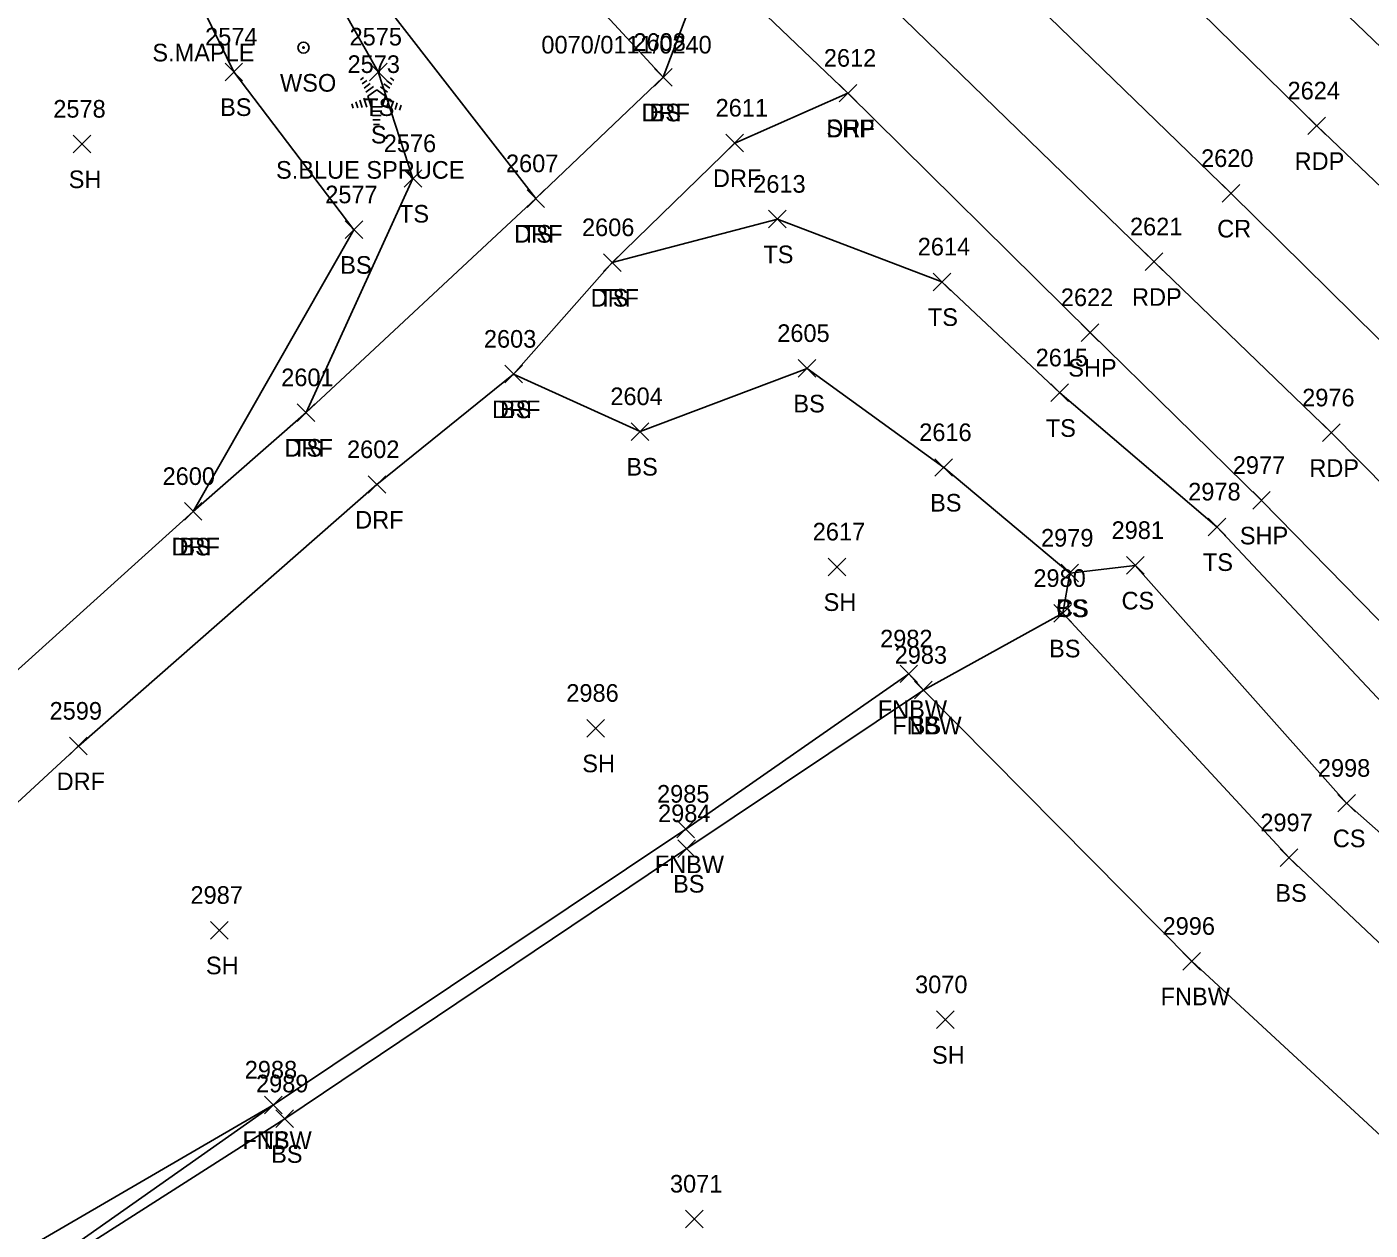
# Model space of a CAD drawing. Extents: x 1472233 to 1475777, y 540726 to 543442.
# Drawn here: x 1473688.8 to 1473841.3, y 542326.8 to 542463.4 of the extents above; entities that cross this region are included whole.
import ezdxf

# ---------------------------------------------------------------- set-up
doc = ezdxf.new("R2010")
doc.units = 0
for name, color, linetype in [('L_A', 7, 'Continuous'), ('L_C', 7, 'Continuous'), ('L_I', 7, 'Continuous'), ('L_TIC', 7, 'Continuous'), ('LELB', 7, 'Continuous'), ('LFNC', 7, 'Continuous'), ('LTC', 7, 'Continuous'), ('P_A', 7, 'Continuous'), ('P_I', 7, 'Continuous'), ('P_TIC', 7, 'Continuous'), ('PET', 7, 'Continuous'), ('PRC', 7, 'Continuous'), ('PSP', 7, 'Continuous'), ('R_A', 7, 'Continuous'), ('R_I', 7, 'Continuous'), ('R_TIC', 7, 'Continuous'), ('RDF', 7, 'Continuous'), ('S_C', 7, 'Continuous'), ('U_A', 7, 'Continuous'), ('UWV', 7, 'Continuous')]:
    doc.layers.add(name, color=color, linetype=linetype)

msp = doc.modelspace()

# ---------------------------------------------------------------- linework, layer by layer
at = {"layer": 'L_TIC'}
for points in [[(1473711.29, 542457.24), (1473713.29, 542459.24)], [(1473713.29, 542457.24), (1473711.29, 542459.24)], [(1473727.69, 542457.24), (1473729.69, 542459.24)], [(1473729.69, 542457.24), (1473727.69, 542459.24)], [(1473760.05, 542456.63), (1473762.05, 542458.63)], [(1473762.05, 542456.63), (1473760.05, 542458.63)], [(1473694.05, 542449.05), (1473696.05, 542451.05)], [(1473696.05, 542449.05), (1473694.05, 542451.05)], [(1473731.63, 542445.14), (1473733.63, 542447.14)], [(1473733.63, 542445.14), (1473731.63, 542447.14)], [(1473745.58, 542442.86), (1473747.58, 542444.86)], [(1473747.58, 542442.86), (1473745.58, 542444.86)], [(1473773, 542440.53), (1473775, 542442.53)], [(1473775, 542440.53), (1473773, 542442.53)], [(1473724.93, 542439.33), (1473726.93, 542441.33)], [(1473726.93, 542439.33), (1473724.93, 542441.33)], [(1473754.26, 542435.6), (1473756.26, 542437.6)], [(1473756.26, 542435.6), (1473754.26, 542437.6)], [(1473791.68, 542433.41), (1473793.68, 542435.41)], [(1473793.68, 542433.41), (1473791.68, 542435.41)], [(1473791.68, 542433.41), (1473793.68, 542435.41)], [(1473793.68, 542433.41), (1473791.68, 542435.41)], [(1473743.06, 542422.94), (1473745.06, 542424.94)], [(1473745.06, 542422.94), (1473743.06, 542424.94)], [(1473776.37, 542423.59), (1473778.37, 542425.59)], [(1473778.37, 542423.59), (1473776.37, 542425.59)], [(1473805.07, 542420.82), (1473807.07, 542422.82)], [(1473807.07, 542420.82), (1473805.07, 542422.82)], [(1473719.49, 542418.57), (1473721.49, 542420.57)], [(1473721.49, 542418.57), (1473719.49, 542420.57)], [(1473757.42, 542416.42), (1473759.42, 542418.42)], [(1473759.42, 542416.42), (1473757.42, 542418.42)], [(1473791.9, 542412.34), (1473793.9, 542414.34)], [(1473793.9, 542412.34), (1473791.9, 542414.34)], [(1473791.9, 542412.34), (1473793.9, 542414.34)], [(1473793.9, 542412.34), (1473791.9, 542414.34)], [(1473706.67, 542407.36), (1473708.67, 542409.36)], [(1473708.67, 542407.36), (1473706.67, 542409.36)], [(1473822.91, 542405.6), (1473824.91, 542407.6)], [(1473824.91, 542405.6), (1473822.91, 542407.6)], [(1473779.76, 542401.06), (1473781.76, 542403.06)], [(1473781.76, 542401.06), (1473779.76, 542403.06)], [(1473813.64, 542401.23), (1473815.64, 542403.23)], [(1473815.64, 542401.23), (1473813.64, 542403.23)], [(1473806.21, 542400.36), (1473808.21, 542402.36)], [(1473808.21, 542400.36), (1473806.21, 542402.36)], [(1473806.21, 542400.36), (1473808.21, 542402.36)], [(1473808.21, 542400.36), (1473806.21, 542402.36)], [(1473805.41, 542395.79), (1473807.41, 542397.79)], [(1473807.41, 542395.79), (1473805.41, 542397.79)], [(1473805.41, 542395.79), (1473807.41, 542397.79)], [(1473807.41, 542395.79), (1473805.41, 542397.79)], [(1473787.93, 542388.92), (1473789.93, 542390.92)], [(1473789.93, 542388.92), (1473787.93, 542390.92)], [(1473787.93, 542388.92), (1473789.93, 542390.92)], [(1473789.93, 542388.92), (1473787.93, 542390.92)], [(1473789.58, 542387.07), (1473791.58, 542389.07)], [(1473791.58, 542387.07), (1473789.58, 542389.07)], [(1473789.58, 542387.07), (1473791.58, 542389.07)], [(1473791.58, 542387.07), (1473789.58, 542389.07)], [(1473752.36, 542382.75), (1473754.36, 542384.75)], [(1473754.36, 542382.75), (1473752.36, 542384.75)], [(1473837.63, 542374.24), (1473839.63, 542376.24)], [(1473839.63, 542374.24), (1473837.63, 542376.24)], [(1473762.6, 542371.3), (1473764.6, 542373.3)], [(1473764.6, 542371.3), (1473762.6, 542373.3)], [(1473762.72, 542369.09), (1473764.72, 542371.09)], [(1473764.72, 542369.09), (1473762.72, 542371.09)], [(1473831.1, 542368.05), (1473833.1, 542370.05)], [(1473833.1, 542368.05), (1473831.1, 542370.05)], [(1473709.63, 542359.82), (1473711.63, 542361.82)], [(1473711.63, 542359.82), (1473709.63, 542361.82)], [(1473820.05, 542356.3), (1473822.05, 542358.3)], [(1473822.05, 542356.3), (1473820.05, 542358.3)], [(1473792.07, 542349.67), (1473794.07, 542351.67)], [(1473794.07, 542349.67), (1473792.07, 542351.67)], [(1473715.79, 542339.99), (1473717.79, 542341.99)], [(1473717.79, 542339.99), (1473715.79, 542341.99)], [(1473715.79, 542339.99), (1473717.79, 542341.99)], [(1473717.79, 542339.99), (1473715.79, 542341.99)], [(1473717.07, 542338.42), (1473719.07, 542340.42)], [(1473719.07, 542338.42), (1473717.07, 542340.42)], [(1473763.58, 542327.05), (1473765.58, 542329.05)], [(1473765.58, 542327.05), (1473763.58, 542329.05)]]:
    msp.add_lwpolyline(points, dxfattribs=at)
at = {"layer": 'LELB'}
for points in [[(1473694.52, 542523.59), (1473709.48, 542491.61), (1473746.58, 542443.86)], [(1473694.52, 542523.59), (1473734.71, 542486.17), (1473761.05, 542457.63)], [(1473673.23, 542513.08), (1473689.8, 542504.27), (1473712.29, 542458.24), (1473725.93, 542440.33), (1473707.67, 542408.36)], [(1473709.48, 542491.61), (1473720.94, 542471.94), (1473728.69, 542458.24), (1473732.63, 542446.14), (1473720.49, 542419.57)], [(1473755.26, 542436.6), (1473774, 542441.53), (1473792.68, 542434.41)], [(1473792.68, 542434.41), (1473806.07, 542421.82), (1473823.91, 542406.6), (1473846.8, 542382.23), (1473883.89, 542347.59), (1473923.06, 542310.01), (1473939.92, 542294.2), (1473980.53, 542254.94), (1474015.06, 542222.57), (1474049.98, 542187.95), (1474097.37, 542139.4), (1474126.3, 542113.18), (1474158.64, 542082.55), (1474192.68, 542050.26)], [(1473744.06, 542423.94), (1473758.42, 542417.42), (1473777.37, 542424.59), (1473792.9, 542413.34)], [(1473792.9, 542413.34), (1473807.21, 542401.36), (1473806.41, 542396.79), (1473832.1, 542369.05), (1473869.82, 542333.48), (1473905.79, 542295.44), (1473926.1, 542278.34), (1473963.69, 542239.58), (1474000.68, 542206.05), (1474031.52, 542172.06), (1474077.5, 542132.04), (1474083.86, 542123.86), (1474077.32, 542112.31)], [(1473807.21, 542401.36), (1473814.64, 542402.23), (1473838.63, 542375.24), (1473877.39, 542340.99), (1473914.07, 542301.43), (1473934.96, 542288.13), (1473972.64, 542247.92), (1474010.39, 542216.95), (1474043.01, 542181.58), (1474086.64, 542136.88), (1474094.57, 542127.48), (1474117.17, 542110.79), (1474125.34, 542095.52), (1474154.93, 542062.15)], [(1473806.41, 542396.79), (1473790.58, 542388.07), (1473763.72, 542370.09), (1473718.07, 542339.42), (1473679.7, 542314.95)], [(1473716.79, 542340.99), (1473677.93, 542318.4), (1473636, 542289.03), (1473572.72, 542255.02), (1473538.31, 542235.47), (1473487.79, 542200.93), (1473468.56, 542187.86), (1473453.73, 542179.12), (1473444.66, 542179)]]:
    msp.add_lwpolyline(points, dxfattribs=at)
at = {"layer": 'LFNC'}
for points in [[(1473788.93, 542389.92), (1473763.6, 542372.3), (1473716.79, 542340.99), (1473679.7, 542314.95), (1473636.91, 542286.2), (1473580.88, 542249.71), (1473545.42, 542224.8), (1473490.4, 542188.54), (1473453.7, 542165.81)], [(1473788.93, 542389.92), (1473790.58, 542388.07), (1473821.05, 542357.3), (1473858.54, 542322.69), (1473895.28, 542286.17), (1473916.03, 542266.76), (1473948.88, 542234.28), (1473995.44, 542188.5), (1474018.95, 542165.4), (1474046.18, 542138.58), (1474056.8, 542130.76), (1474077.32, 542112.31), (1474080.42, 542109.11)]]:
    msp.add_lwpolyline(points, dxfattribs=at)
at = {"layer": 'LTC'}
for p, q in [((1473726.66, 542457.33), (1473727.01, 542457.59)), ((1473726.87, 542456.87), (1473727.4, 542457.25)), ((1473727.08, 542456.4), (1473727.78, 542456.91)), ((1473727.29, 542455.93), (1473728.16, 542456.57)), ((1473727.51, 542455.48), (1473728.52, 542456.21)), ((1473728.52, 542456.21), (1473729.52, 542455.49)), ((1473728.94, 542456.53), (1473729.75, 542455.94)), ((1473729.31, 542456.88), (1473729.99, 542456.38)), ((1473729.68, 542457.22), (1473730.23, 542456.82)), ((1473730.06, 542457.57), (1473730.47, 542457.27)), ((1473726.14, 542454.83), (1473726.36, 542454.18)), ((1473726.6, 542455.04), (1473726.87, 542454.21)), ((1473727.06, 542455.26), (1473727.39, 542454.24)), ((1473727.51, 542455.48), (1473727.9, 542454.29)), ((1473729.52, 542455.49), (1473729.13, 542454.29)), ((1473729.96, 542455.22), (1473729.62, 542454.18)), ((1473730.4, 542454.97), (1473730.11, 542454.08)), ((1473730.85, 542454.72), (1473730.61, 542453.99)), ((1473725.69, 542454.61), (1473725.84, 542454.14)), ((1473729.13, 542454.29), (1473727.9, 542454.29)), ((1473729.09, 542453.79), (1473727.94, 542453.79)), ((1473729.01, 542453.29), (1473728.02, 542453.29)), ((1473731.29, 542454.47), (1473731.1, 542453.89)), ((1473728.92, 542452.79), (1473728.09, 542452.79)), ((1473728.84, 542452.29), (1473728.16, 542452.29))]:
    msp.add_line(p, q, dxfattribs=at)
at = {"layer": 'P_TIC'}
for points in [[(1473781.02, 542454.83), (1473783.02, 542456.83)], [(1473783.02, 542454.83), (1473781.02, 542456.83)], [(1473834.24, 542451.12), (1473836.24, 542453.12)], [(1473836.24, 542451.12), (1473834.24, 542453.12)], [(1473824.51, 542443.45), (1473826.51, 542445.45)], [(1473826.51, 542443.45), (1473824.51, 542445.45)], [(1473815.78, 542435.69), (1473817.78, 542437.69)], [(1473817.78, 542435.69), (1473815.78, 542437.69)], [(1473808.5, 542427.66), (1473810.5, 542429.66)], [(1473810.5, 542427.66), (1473808.5, 542429.66)], [(1473835.91, 542416.28), (1473837.91, 542418.28)], [(1473837.91, 542416.28), (1473835.91, 542418.28)], [(1473827.97, 542408.61), (1473829.97, 542410.61)], [(1473829.97, 542408.61), (1473827.97, 542410.61)]]:
    msp.add_lwpolyline(points, dxfattribs=at)
at = {"layer": 'PET'}
for points in [[(1473504.62, 542776.33), (1473550.32, 542731.61), (1473584.84, 542698.3), (1473608.01, 542675.08), (1473646.67, 542637.68), (1473674.93, 542609.37), (1473701.59, 542583.63), (1473729.62, 542555.98), (1473768.46, 542518.15), (1473803.13, 542483.63), (1473835.24, 542452.12), (1473854.12, 542434.15), (1473878.03, 542410.14), (1473913.11, 542376.24), (1473951.32, 542338.39), (1473966.93, 542323.54), (1474008.37, 542283), (1474040.51, 542251.21), (1474079.09, 542215.26), (1474152.53, 542143.43), (1474186.7, 542109.47), (1474221.34, 542076.07), (1474257.17, 542041.35)], [(1473486.93, 542759.48), (1473533.41, 542713.5), (1473568.24, 542680.61), (1473591.29, 542657.02), (1473629.02, 542620.51), (1473657.65, 542592.3), (1473684.65, 542566.35), (1473712.07, 542539.16), (1473750.99, 542501.36), (1473781.95, 542470.51), (1473816.78, 542436.69), (1473836.91, 542417.28), (1473859.76, 542394.19), (1473895.18, 542360.02), (1473933.99, 542321.38), (1473950.56, 542305.13), (1473990.91, 542266.49), (1474025.14, 542233.4), (1474060.45, 542198.14), (1474133.98, 542127.35), (1474169.03, 542092.64), (1474239.7, 542023.8)]]:
    msp.add_lwpolyline(points, dxfattribs=at)
at = {"layer": 'PRC'}
msp.add_lwpolyline([(1473496.06, 542767.15), (1473541.59, 542723.23), (1473576.69, 542689.04), (1473599.45, 542666.09), (1473638, 542628.82), (1473666.22, 542601.06), (1473693.18, 542575.28), (1473720.82, 542547.73), (1473759.64, 542509.32), (1473791.5, 542477.44), (1473825.51, 542444.45), (1473844.96, 542425.29), (1473869.12, 542402.24), (1473904.25, 542367.71), (1473942.02, 542329.58), (1473959.56, 542314.37), (1473999.68, 542274.85), (1474033.6, 542242.12), (1474069.35, 542206.93), (1474143.1, 542135.36), (1474177.51, 542101.4), (1474248.4, 542032.72)], dxfattribs=at)
at = {"layer": 'PSP'}
for points in [[(1473511.53, 542783.65), (1473557.71, 542738.52), (1473591.71, 542705.85), (1473614.8, 542682.52), (1473653.25, 542645.69), (1473682.39, 542616.78), (1473708.77, 542591.71), (1473737.42, 542563.39), (1473776.1, 542525.9), (1473801.03, 542501.12), (1473821.16, 542481.55), (1473851.91, 542452.04), (1473882.06, 542422.12), (1473920.54, 542384.18), (1473958.97, 542346.58), (1473974.8, 542332.02), (1474016, 542291.37), (1474048.58, 542260.06), (1474087.68, 542221.94), (1474123.03, 542187.8), (1474161.37, 542151.41), (1474230.43, 542083.96), (1474265.44, 542049.86)], [(1473477.23, 542750.94), (1473505.7, 542725.54), (1473535.93, 542696.72), (1473560.62, 542672.69), (1473579.24, 542654.93), (1473584.38, 542649.62), (1473621.74, 542613.87), (1473650.73, 542585.54), (1473678.25, 542559.11), (1473685.14, 542552.29), (1473704.13, 542532.51), (1473743.26, 542493.38), (1473766.11, 542471.02), (1473782.02, 542455.83), (1473809.5, 542428.66), (1473828.97, 542409.61), (1473851.62, 542386.5)]]:
    msp.add_lwpolyline(points, dxfattribs=at)
at = {"layer": 'R_TIC'}
for points in [[(1473760.05, 542456.63), (1473762.05, 542458.63)], [(1473762.05, 542456.63), (1473760.05, 542458.63)], [(1473781.02, 542454.83), (1473783.02, 542456.83)], [(1473783.02, 542454.83), (1473781.02, 542456.83)], [(1473768.16, 542449.17), (1473770.16, 542451.17)], [(1473770.16, 542449.17), (1473768.16, 542451.17)], [(1473745.58, 542442.86), (1473747.58, 542444.86)], [(1473747.58, 542442.86), (1473745.58, 542444.86)], [(1473754.26, 542435.6), (1473756.26, 542437.6)], [(1473756.26, 542435.6), (1473754.26, 542437.6)], [(1473743.06, 542422.94), (1473745.06, 542424.94)], [(1473745.06, 542422.94), (1473743.06, 542424.94)], [(1473719.49, 542418.57), (1473721.49, 542420.57)], [(1473721.49, 542418.57), (1473719.49, 542420.57)], [(1473727.53, 542410.41), (1473729.53, 542412.41)], [(1473729.53, 542410.41), (1473727.53, 542412.41)], [(1473706.67, 542407.36), (1473708.67, 542409.36)], [(1473708.67, 542407.36), (1473706.67, 542409.36)], [(1473693.64, 542380.72), (1473695.64, 542382.72)], [(1473695.64, 542380.72), (1473693.64, 542382.72)]]:
    msp.add_lwpolyline(points, dxfattribs=at)
at = {"layer": 'RDF'}
for points in [[(1473557.34, 542291.42), (1473602.78, 542321.48), (1473637.72, 542349.72), (1473663.06, 542367.45), (1473685.86, 542388.66), (1473707.67, 542408.36), (1473720.49, 542419.57), (1473746.58, 542443.86), (1473761.05, 542457.63), (1473766.11, 542471.02)], [(1473557.34, 542291.42), (1473566.04, 542281.68), (1473609.66, 542311.05), (1473648.39, 542341.34), (1473669.78, 542358.78), (1473694.64, 542381.72), (1473728.53, 542411.41), (1473744.06, 542423.94), (1473755.26, 542436.6), (1473769.16, 542450.17), (1473782.02, 542455.83)]]:
    msp.add_lwpolyline(points, dxfattribs=at)
at = {"layer": 'UWV'}
for radius in [0.625, 0.0833]:
    msp.add_circle((1473720.2, 542461), radius, dxfattribs=at)

# ---------------------------------------------------------------- texts
at = {"layer": 'L_A'}
for s, p in [('BS', (1473710.73, 542453.24)), ('TS', (1473727.1, 542453.24)), ('BS', (1473759.49, 542452.63)), ('S', (1473727.85, 542450.12)), ('SH', (1473693.54, 542445.05)), ('TS', (1473731.04, 542441.14)), ('TS', (1473744.99, 542438.86)), ('TS', (1473772.41, 542436.53)), ('BS', (1473724.37, 542435.33)), ('TS', (1473753.67, 542431.6)), ('TS', (1473791.09, 542429.41)), ('TS', (1473791.09, 542429.41)), ('BS', (1473775.82, 542419.59)), ('BS', (1473742.5, 542418.94)), ('TS', (1473804.48, 542416.82)), ('TS', (1473718.9, 542414.57)), ('BS', (1473756.86, 542412.42)), ('BS', (1473791.34, 542408.34)), ('BS', (1473791.34, 542408.34)), ('BS', (1473706.11, 542403.36)), ('TS', (1473822.32, 542401.6)), ('SH', (1473779.25, 542397.06)), ('CS', (1473805.65, 542396.36)), ('BS', (1473805.65, 542396.36)), ('CS', (1473813.08, 542397.23)), ('BS', (1473804.85, 542391.79)), ('BS', (1473804.85, 542391.79)), ('FNBW', (1473785.4, 542384.92)), ('FNBW', (1473785.4, 542384.92)), ('FNBW', (1473787.05, 542383.07)), ('BS', (1473789.02, 542383.07)), ('SH', (1473751.85, 542378.75)), ('CS', (1473837.07, 542370.24)), ('FNBW', (1473760.08, 542367.3)), ('BS', (1473762.16, 542365.09)), ('BS', (1473830.54, 542364.05)), ('SH', (1473709.12, 542355.82)), ('FNBW', (1473817.52, 542352.3)), ('SH', (1473791.56, 542345.67)), ('FNBW', (1473713.26, 542335.99)), ('TS', (1473715.2, 542335.99)), ('BS', (1473716.52, 542334.42))]:
    msp.add_text(s, height=2, dxfattribs=at).set_placement(p)
at = {"layer": 'L_C'}
for s, p in [('S.MAPLE', (1473703.04, 542459.43)), ('S.BLUE SPRUCE', (1473717.08, 542446.12))]:
    msp.add_text(s, height=2, dxfattribs=at).set_placement(p)
at = {"layer": 'L_I'}
for s, p in [('2574', (1473709.03, 542461.24)), ('2575', (1473725.43, 542461.24)), ('2608', (1473757.66, 542460.63)), ('2573', (1473725.2, 542458.12)), ('2578', (1473691.79, 542453.05)), ('2576', (1473729.31, 542449.14)), ('2607', (1473743.19, 542446.86)), ('2613', (1473771.26, 542444.53)), ('2577', (1473722.67, 542443.33)), ('2606', (1473751.82, 542439.6)), ('2614', (1473789.94, 542437.41)), ('2614', (1473789.94, 542437.41)), ('2603', (1473740.68, 542426.94)), ('2605', (1473773.99, 542427.59)), ('2615', (1473803.33, 542424.82)), ('2601', (1473717.67, 542422.57)), ('2604', (1473755.04, 542420.42)), ('2616', (1473790.11, 542416.34)), ('2616', (1473790.11, 542416.34)), ('2600', (1473704.2, 542411.36)), ('2978', (1473820.65, 542409.6)), ('2617', (1473778.02, 542405.06)), ('2979', (1473803.94, 542404.36)), ('2979', (1473803.94, 542404.36)), ('2981', (1473811.95, 542405.23)), ('2980', (1473803.07, 542399.79)), ('2980', (1473803.07, 542399.79)), ('2982', (1473785.67, 542392.92)), ('2982', (1473785.67, 542392.92)), ('2983', (1473787.32, 542391.07)), ('2983', (1473787.32, 542391.07)), ('2986', (1473750.04, 542386.75)), ('2998', (1473835.37, 542378.24)), ('2985', (1473760.34, 542375.3)), ('2984', (1473760.46, 542373.09)), ('2997', (1473828.84, 542372.05)), ('2987', (1473707.37, 542363.82)), ('2996', (1473817.74, 542360.3)), ('3070', (1473789.64, 542353.67)), ('2988', (1473713.53, 542343.99)), ('2988', (1473713.53, 542343.99)), ('2989', (1473714.81, 542342.42)), ('3071', (1473761.81, 542331.05))]:
    msp.add_text(s, height=2, dxfattribs=at).set_placement(p)
at = {"layer": 'LTC'}
msp.add_text('.', height=1.04, rotation=270, dxfattribs=at).set_placement((1473728.4, 542455.23))
at = {"layer": 'P_A'}
for s, p in [('SHP', (1473779.56, 542450.83)), ('RDP', (1473832.73, 542447.12)), ('CR', (1473823.94, 542439.45)), ('RDP', (1473814.27, 542431.69)), ('SHP', (1473807.03, 542423.66)), ('RDP', (1473834.4, 542412.28)), ('SHP', (1473826.51, 542404.61))]:
    msp.add_text(s, height=2, dxfattribs=at).set_placement(p)
at = {"layer": 'P_I'}
for s, p in [('2612', (1473779.28, 542458.83)), ('2624', (1473831.93, 542455.12)), ('2620', (1473822.11, 542447.45)), ('2621', (1473814.04, 542439.69)), ('2622', (1473806.19, 542431.66)), ('2976', (1473833.59, 542420.28)), ('2977', (1473825.71, 542412.61))]:
    msp.add_text(s, height=2, dxfattribs=at).set_placement(p)
at = {"layer": 'R_A'}
for p in [(1473758.58, 542452.63), (1473779.56, 542450.83), (1473766.69, 542445.17), (1473744.12, 542438.86), (1473752.8, 542431.6), (1473741.6, 542418.94), (1473718.03, 542414.57), (1473726.07, 542406.41), (1473705.21, 542403.36), (1473692.17, 542376.72)]:
    msp.add_text('DRF', height=2, dxfattribs=at).set_placement(p)
at = {"layer": 'R_I'}
for s, p in [('2608', (1473757.66, 542460.63)), ('2612', (1473779.28, 542458.83)), ('2611', (1473766.99, 542453.17)), ('2607', (1473743.19, 542446.86)), ('2606', (1473751.82, 542439.6)), ('2603', (1473740.68, 542426.94)), ('2601', (1473717.67, 542422.57)), ('2602', (1473725.14, 542414.41)), ('2600', (1473704.2, 542411.36)), ('2599', (1473691.37, 542384.72))]:
    msp.add_text(s, height=2, dxfattribs=at).set_placement(p)
at = {"layer": 'S_C'}
msp.add_text('0070/0111/0240', height=2, dxfattribs=at).set_placement((1473747.21, 542460.33))
at = {"layer": 'U_A'}
msp.add_text('WSO', height=2, dxfattribs=at).set_placement((1473717.53, 542456))

doc.saveas('drawing.dxf')
